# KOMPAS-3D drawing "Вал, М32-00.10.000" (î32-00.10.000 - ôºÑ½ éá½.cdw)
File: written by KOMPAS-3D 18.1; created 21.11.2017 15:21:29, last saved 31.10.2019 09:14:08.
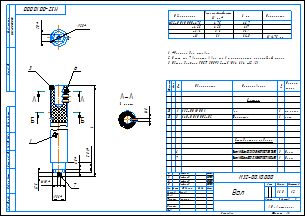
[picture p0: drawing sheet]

Sheet 1: A3, landscape

Document properties: Полное имя файла: D:\Magna\Магна Ins\Магна ins 32\Для Караби\М32-00.10.000 - Узел Вал.cdw; Масса: 1.67698

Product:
- Part/product: Вал  | designation М32-00.10.000  | pos. 0
    Масса: 1.67698
    Раздел спецификации: Сборочные единицы
    Форматы листов документа: A3
    source file: C:\Users\User\Desktop\Вал _ М32-00.10.000.spw, М32-00.10.000 - Вал.cdw
  - Component [detail]: Вал  | designation М32-00.10.001  | pos. 1
      Масса: 1.30054
      Раздел спецификации: Детали
      Форматы листов документа: A3
      Примечание: см. заказ
      Зона: 2A
      source file: М32-00.10.001 - Вал.cdw, М32-00.10.001 - Вал.m3d
  - Component [standard]: Винт A.М10-6gx30.21.12Х18Н10Т ГОСТ 11074-93  | pos. 7
      Материал: Сталь 12Х18Н10Т ГОСТ 5632-72 (density 1000 kg/m3)
      Масса: 0.01408
      Раздел спецификации: Стандартные изделия
      Примечание: Нерж.
      Зона: 2A
      additional columns: А.М10-6gx30.21.12Х18Н10Т; Сталь 12Х18Н10Т ГОСТ 5632-72
      source file: C:\Program Files\ASCON\KOMPAS-3D v18\Libs\PartLib\DATA\VAULT\methods\kompas\3d\PLib_Screw_GOST_11074-84_900.m3d
  - Component [standard]: Винт A.М8-6gx20.21.12Х18Н10Т ГОСТ 8878-93  | pos. 6
      Материал: Сталь 12Х18Н10Т ГОСТ 5632-72 (density 1000 kg/m3)
      Масса: 0.0054
      Раздел спецификации: Стандартные изделия
      Примечание: Нерж.
      Зона: 2A
      additional columns: А.М8-6gx20.21.12Х18Н10Т; Сталь 12Х18Н10Т ГОСТ 5632-72
      source file: C:\Program Files\ASCON\KOMPAS-3D v18\Libs\PartLib\DATA\VAULT\methods\kompas\3d\PLib_Screw_GOST_8878-84_900.m3d
  - Component [detail]: Фиксатор  | designation М40-00.10.002-02  | pos. 3
      Материал: Сталь 12Х18Н10Т ГОСТ 5632-72 (density 7900 kg/m3)
      Масса: 0.346158
      Раздел спецификации: Детали
      Форматы листов документа: A3
      Примечание: заим.
      source file: C:\Users\Kon\Desktop\Переработка Лифлянд\Магна ins 40\М40-00.10.002 - Фиксатор.cdw, М40-00.10.002 - Фиксатор.m3d
  - Component [standard]: Винт A.М8-6gx20.21.12Х18Н10Т ГОСТ 8878-93  | qty 2  | pos. 6
      Материал: Сталь 12Х18Н10Т ГОСТ 5632-72 (density 1000 kg/m3)
      Масса: 0.0054
      Раздел спецификации: Стандартные изделия
      Примечание: Нерж.
      additional columns: А.М8-6gx20.21.12Х18Н10Т; Сталь 12Х18Н10Т ГОСТ 5632-72
      source file: C:\Program Files\ASCON\KOMPAS-3D v18\Libs\PartLib\DATA\VAULT\methods\kompas\3d\PLib_Screw_GOST_8878-84_900.m3d

Title block, sheet 1: Наименование: Вал; designation: М32-00.10.000; Масса: 1,68; scale: 1:2; Количество листов документа: 1; organisation: АО «Астерион»; Форматы листов документа: A3; stored path: D:\Отработать\Магна 40\Чертежи\М40-00.10.000 - Вал М10.cdw; Разработал: Милов; Т. контр.: Лучихин

Views: Вид 1, Спереди, Проекционный вид 3, Местный разрез 1, Разрез Б-Б, Разрез А-А
Referenced files in D:\Отработать\Магна 40\3Д\: М40-00.10.000 - Вал.a3d, 8М40-00.10.002 - Фиксатор.m3d, М40-00.10.001 - Вал.m3d
Referenced files in D:\Magna\Магна Ins\Магна ins 32\Для Караби\: М32-00.10.000 - Узел Вал.a3d, М32-00.10.001 - Вал.m3d, М32-00.10.001 - Вал.cdw, М40-00.10.002 - Фиксатор.m3d
Referenced files in C:\Users\Kon\Desktop\Переработка Лифлянд\Магна ins 40\: М40-00.10.002 - Фиксатор.cdw, М40-00.10.002 - Фиксатор.m3d
Referenced files in C:\Program Files\ASCON\KOMPAS-3D v18\Libs\PartLib\DATA\VAULT\methods\kompas\3d\: PLib_Screw_GOST_11074-84_900.m3d, PLib_Screw_GOST_8878-84_900.m3d
Referenced files in C:\Program Files\ASCON\KOMPAS-3D V16\Libs\PartLib\DATA\VAULT\Methods\kompas\3d\: PLib_Screw_GOST_11074-84_900.m3d, PLib_Screw_GOST_8878-84_900.m3d
Referenced files in Z:\Магна\Магна Ins\Магна ins 32\: М32-00.10.002 - Фиксатор.m3d, М32-00.10.001 - Вал.m3d
Referenced files in C:\Program Files\ASCON\KOMPAS-3D V16\Libs\PartLib\DATA\vault\Methods\Kompas\3D\: PLib_Screw_GOST_8878-84_900.m3d
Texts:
  Длина погружной части
  L1, мм*
  L, мм
  L1 475 мм
  см. заказ
  Винт A.М10-6gx30.21.12Х18Н10Т ГОСТ 11074-93
  Крепежное изделие ГОСТ
  Винт
  ГОСТ
  Нерж.
  Винт A.М8-6gx20.21.12Х18Н10Т ГОСТ 8878-93
  Фиксатор
  заим.
  Лифлянд
Dimensions and other numbers on the sheet: 28; 20; 12,5; 36; 8,5; 1; 6; 7; 10; 475; 467; -425; -375; 425; 375; 417; 367; 28,1; 3; 3 места; 8; 4; 21; 12Х18Н10Т; 019; 1:2; 1,68; 5; 09.09.2019; 30.10.2019; 12.07.2019; 22.08.2019; 02

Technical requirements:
  *Размеры для справок.
  Винт поз. 7  вклеить в вал поз. 1  с применением эпоксидной смолы.
  Общие допуски ГОСТ 30893.2-тК (H14, h14,  t2/2).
